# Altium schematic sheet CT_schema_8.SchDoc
size 308 x 210 mm
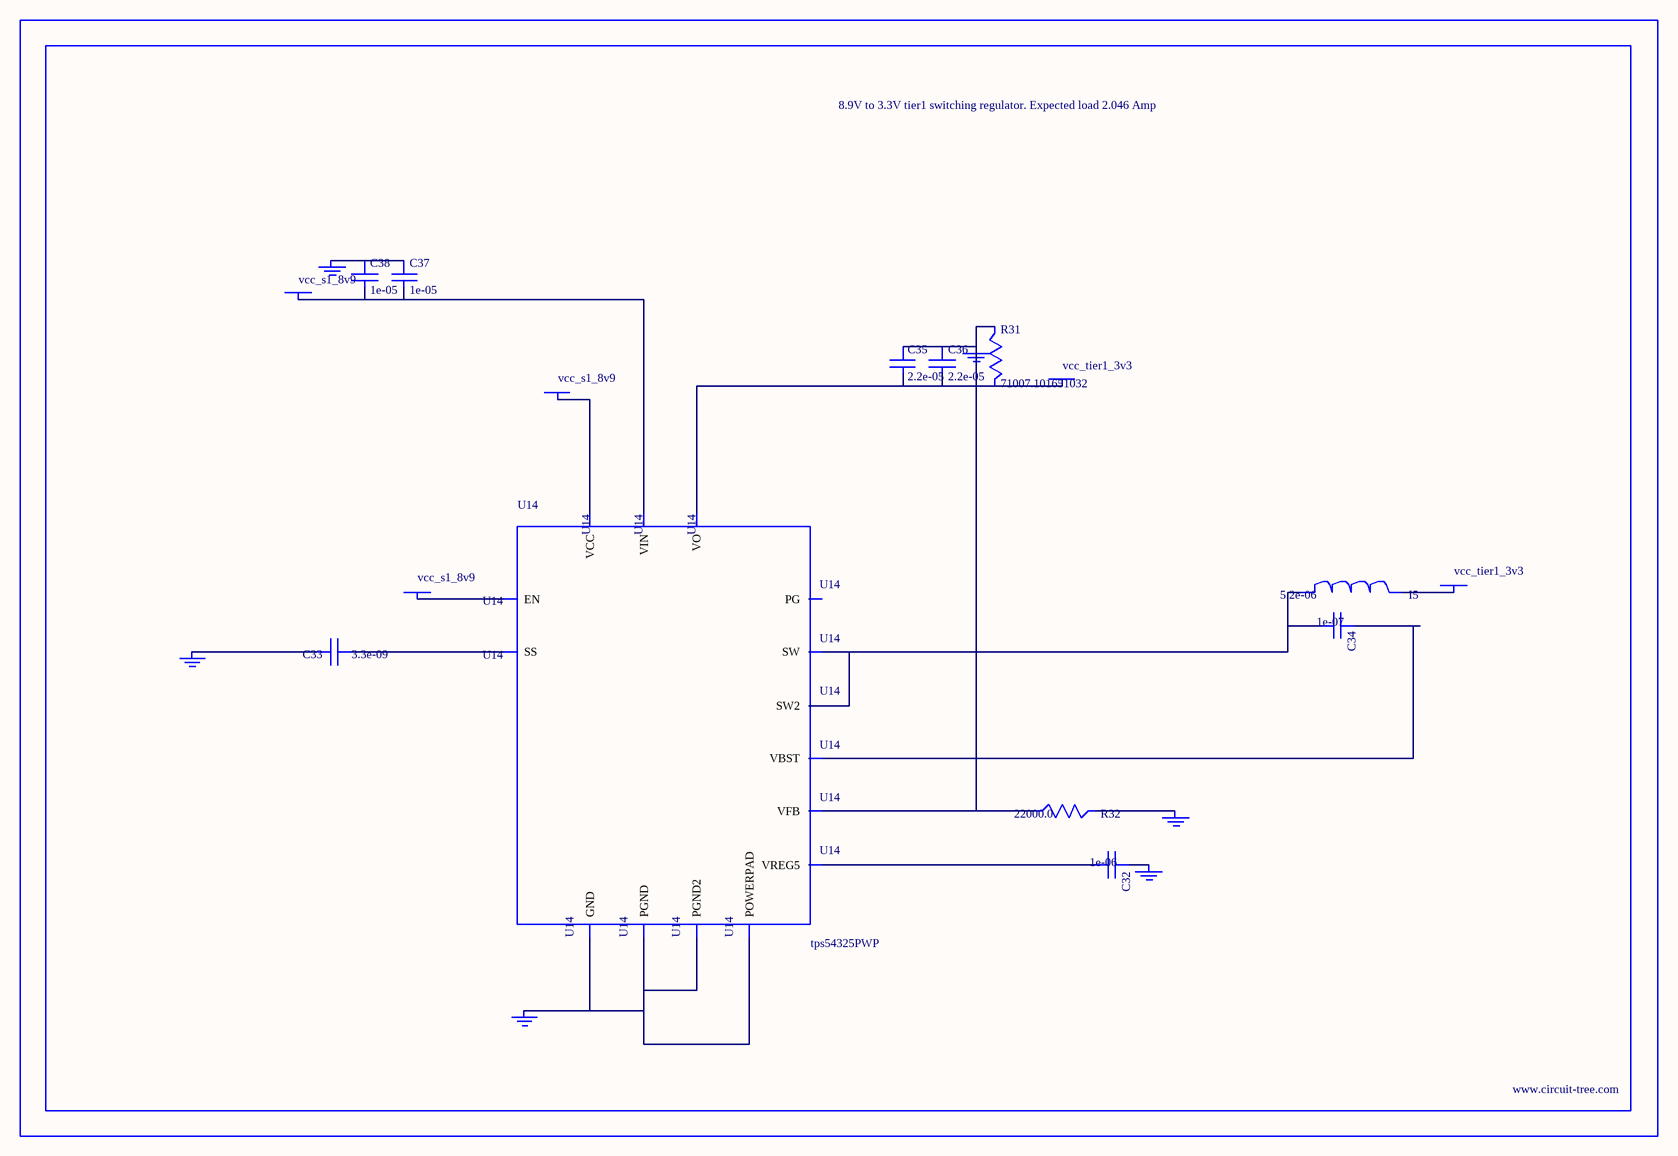
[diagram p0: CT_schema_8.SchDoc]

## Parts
BORDER7  (no value)
C32  1e-06  [C0603]
C33  3.3e-09  [C0402]
C34  1e-07  [C0402]
C35  2.2e-05  [C1210]
C36  2.2e-05  [C1210]
C37  1e-05  [C1206]
C38  1e-05  [C1206]
GND_INSTANCE_7_0  (no value)
GND_INSTANCE_7_1  (no value)
GND_INSTANCE_7_2  (no value)
GND_INSTANCE_7_3  (no value)
GND_INSTANCE_7_4  (no value)
GND_INSTANCE_7_5  (no value)
I5  5.2e-06  [DR1040]
POWER_INSTANCE_7_0  vcc_tier1_3v3
POWER_INSTANCE_7_1  vcc_s1_8v9
POWER_INSTANCE_7_2  vcc_tier1_3v3
POWER_INSTANCE_7_3  vcc_s1_8v9
POWER_INSTANCE_7_4  vcc_s1_8v9
R31  71007.101651032  [R0603]
R32  22000.0  [R0603]
U14  tps54325PWP  [HTSSOP14]

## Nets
NetC32_1: C32.1 GND_INSTANCE_7_2.0(GND)
NetC32_2: C32.2 U14.3(VREG5)
NetC33_1: C33.1 U14.4(SS)
NetC33_2: C33.2 GND_INSTANCE_7_3.0(GND)
NetC34_1: C34.1 U14.12(VBST)
NetC34_2: C34.2 I5.1 U14.10(SW) U14.11(SW2)
NetC35_1: C35.1 C36.1 GND_INSTANCE_7_0.0(GND) R31.1 R32.1 U14.2(VFB)
NetC35_2: C35.2 C36.2 POWER_INSTANCE_7_0.0(PWR) R31.2 U14.1(VO)
NetC37_1: C37.1 C38.1 GND_INSTANCE_7_5.0(GND)
NetC37_2: C37.2 C38.2 POWER_INSTANCE_7_3.0(PWR) U14.13(VIN)
NetGND_INSTANCE_7_1_0: GND_INSTANCE_7_1.0(GND) R32.2
NetGND_INSTANCE_7_4_0: GND_INSTANCE_7_4.0(GND) U14.5(GND) U14.8(PGND) U14.9(PGND2) U14.15(POWERPAD)
NetI5_2: I5.2 POWER_INSTANCE_7_2.0(PWR)
NetPOWER_INSTANCE_7_1_0: POWER_INSTANCE_7_1.0(PWR) U14.7(EN)
NetPOWER_INSTANCE_7_4_0: POWER_INSTANCE_7_4.0(PWR) U14.14(VCC)

Not connected (* = marked no-connect by the designer): U14 6(PG)

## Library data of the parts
BORDER7 = BORDER_PAGE7
C32 = C0603C105K3RACTU
C33 = C0402C332K3RAC
C34 = C0402C104K3RACTU
C35 C36 = GRM32ER61E226ME15L
C37 C38 = C1206C106K3RACTU
GND_INSTANCE_7_0-GND_INSTANCE_7_5 = GND
I5 = DR1040-5R2-R
POWER_INSTANCE_7_0-POWER_INSTANCE_7_4 = PWR
R31 = R31
R32 = RC0603JR-0722KL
